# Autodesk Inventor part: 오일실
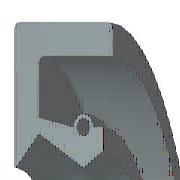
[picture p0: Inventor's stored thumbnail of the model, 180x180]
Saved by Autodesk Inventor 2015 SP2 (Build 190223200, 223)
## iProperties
IsCustomPart: 0
Manager: KYOUNG IL JANG
Company: 한국ATC센터
Created: 2009-02
Part Number: 오일실
Material: 고무
Description: 오일-실
Document SubType Name: Modeling
Standard: KS B 2804
Standards Organization: KS
Language: ko-KR
Size Designation: D - 20 35 8
Categories: <MemberInstance><Categories><Category DisplayName="샤프트 부품" InternalName="7f7aeb1f-a693-4053-b835-cee3144e0d98" Mnemonic="SHFT"><Category DisplayName="실링" Intern
Density: 0.93 g/cm^3
Checked By: KYOUNG IL JANG
Vendor: CBT Solutions
Designer: KYOUNG IL JANG
Appearance: 고무 - 검은색 - 버전 1.1
Author: KYOUNG IL JANG
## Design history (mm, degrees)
revolve "본체" stored, may be unused: angle "d17" = 90 deg
revolve "스프링1" stored, may be unused: angle "d18" = 90 deg
body "Solid1"
sketch "스케치1"
  geometry: L1 (0, 17.5)-(8, 17.5); L2 (8, 15.75)-(1.75, 15.75); L3 (1.75, 11.75)-(4.9, 10); L4 (4.9, 10)-(0, 10); L5 (0, 0)-(9.586, 0) reference; L6 (4.9, 10)-(6.3, 10.875); L7 (0, 18)-(0, -3) reference; L8 (-1.941, 0)-(11.507, 0) reference; L9 (4.2, 12.1)-(1.75, 12.71); L10 (1.75, 12.71)-(1.75, 15.75); L11 (0, 17.5)-(0, 10.088); L12 (4.9, 10)-(0, 10); L13 (1.75, 11.75)-(0.152, 10.028); L14 (8, 17.5)-(8, 15.75); L15 (5.6, 12.1)-(6.3, 12.1); L16 (6.3, 12.1)-(6.3, 10.875); C1 r 0.455 at (4.9, 12.1); A1 r 0.7 centre (4.9, 12.1) between (5.6, 12.1) and (4.2, 12.1); A2 r 0.088 centre (0.088, 10.088) between (0, 10.088) and (0.152, 10.028); 1 further point
  constraints: 28 end point, 5 horizontal alignment, 5 point on line, 4 point on circle, 4 vertical alignment, 3 centre point, 3 tangent, 2 collinear, 2 horizontal, 2 perpendicular, 1 coincident, 1 parallel
  dimensions: "d0" = 35 diameter of L1 L5 (= SD2); "d1" = 1.75 distance of L1.end L2.start (= SD); "d2" = 0.91 diameter of C1 (= SPDI); "d3" = 1.4 diameter of A1 (= SPDA); "d4" = 20 diameter of L3.end L5 (= NND); "d5" = 23.5 diameter of L3.start L5 (= TKDM); "d7" = 25.42 diameter of L9.end L5 (= TKDM + 0.24 x SWDT); "d8" = 1.75 distance between parallel lines of L11 L10 (= SD); "d9" = 4.9 distance from line of L11 C1.centre (= SPDST); "d10" = 24.2 diameter of C1.centre L5 (= HLDM); "d11" = 0.0875 radius of A2 (= 0.25 x LAB); "d12" = 6.3 distance between parallel lines of L11 L16 (= SDI); "d13" = 21.75 diameter of L6.end L5 (= ABDM); "d14" = 8 distance from line of L11 L1.end (= SWDT)
fillet "모깎기1" dims "d6" = 0.3 (= RR)
other parameters: "SD2" = 35 [user parameter; used in 1 equation term], "SWDT" = 8 [user parameter; used in 2 equation terms], "RR" = 0.3 [user parameter; used in 1 equation term], "SD" = 1.75 [user parameter; used in 2 equation terms], "NND" = 20 [user parameter; used in 1 equation term], "SPDA" = 1.4 [user parameter; used in 1 equation term], "SPDI" = 0.91 [user parameter; used in 1 equation term], "TKDM" = 23.5 [user parameter; used in 2 equation terms], "HLDM" = 24.2 [user parameter; used in 1 equation term], "ABDM" = 21.75 [user parameter; used in 1 equation term], "SDI" = 6.3 [user parameter; used in 1 equation term], "SPDST" = 4.9 [user parameter; used in 1 equation term], "LAB" = 0.35 [user parameter; used in 1 equation term], "d15" = 0, "d16" = 0, "d19" = 0
